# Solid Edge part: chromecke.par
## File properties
Author: ra-11
Template: Normal.par
Last saved by: ra-11
Revision: 2
Application: Solid Edge
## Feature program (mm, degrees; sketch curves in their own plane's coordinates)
sketch for "unnamed Protrusion 1" plane through (0, 0, 0) normal (0, 0, 1) x-axis (1, 0, 0)
  line (-125, -100) -> (125, -100)
  line (125, -100) -> (125, 100)
  line (125, 100) -> (-125, 100)
  line (-125, 100) -> (-125, -100)
extrude "unnamed Protrusion 1" add finite 3 along +normal
sketch for "unnamed Protrusion 2" plane through (0, 0, 3) normal (0, 0, 1) x-axis (1, 0, 0)
  line (125, 100) -> (-125, 100)
  line (-125, 100) -> (-125, -100)
  line (-125, -100) -> (-123, -100)
  line (-123, -100) -> (-123, 98)
  line (-123, 98) -> (125, 98)
  line (125, 98) -> (125, 100)
extrude "unnamed Protrusion 2" add finite 150 along +normal
